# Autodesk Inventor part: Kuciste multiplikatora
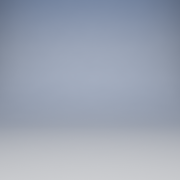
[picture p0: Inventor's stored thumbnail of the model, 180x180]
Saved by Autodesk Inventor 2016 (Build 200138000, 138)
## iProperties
Created: 2015-08
Part Number: Kuciste multiplikatora
Material: Generic
Document SubType Name: Modeling
Designer: Ugljesa
Density: 1 g/cm^3
Appearance: Default
Author: Ugljesa
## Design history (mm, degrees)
sketch "Sketch1"
  geometry: L1 (-70.533, -35.328)-(-30.533, -35.328); L2 (-30.533, -35.328)-(9.99, -69.331); L3 (-70.533, 44.672)-(-20.533, 44.672); L4 (-20.533, 44.672)-(38.788, 60.567); L5 (40.082, 55.737)-(-19.874, 39.672); L6 (-19.874, 39.672)-(-70.533, 39.672); L7 (-70.533, -30.328)-(-28.713, -30.328); L8 (-28.713, -30.328)-(13.204, -65.5); L9 (-70.533, 44.672)-(-70.533, 39.672); L10 (-70.533, -35.328)-(-70.533, -30.328); C1 r 12.5 at (58.199, -11.877) reference; A1 r 75 centre (58.199, -11.877) between (9.99, -69.331) and (38.788, 60.567); A2 r 70 centre (58.199, -11.877) between (13.204, -65.5) and (40.082, 55.737); 1 further point
  constraints: 20 end point, 4 point on circle, 2 centre point, 2 tangent, 2 vertical, 1 coincident, 1 horizontal, 3 other
  dimensions: "d0" = 80 distance of L3.start L1.start; "d1" = 15 deg angle of L4 L3; "d2" = 40 deg angle of L1 L2; "d3" = 75 radius of A1; "d4" = 50 distance of L3.start L3.end; "d5" = 40 distance of L1.start L1.end; "d6" = 5 radial gap between concentric circles of A1 A2; "d23" = 70 distance between parallel lines of L7 L6; "d25" = 5 distance between parallel lines of L4 L5
  node "Reference1"
workplane "Work Plane1"
workplane "Work Plane2"
extrude "Extrusion1" new body sketch "Sketch1" stored distance "d7" = 19.75; taper "d8" = 0 deg
sketch "Sketch2"
  geometry: L1 (120, 37)-(205, 25.054); L2 (205, 25.054)-(205, 37); L3 (205, 37)-(120, 37); L4 (50, 0)-(109.321, 0) reference; L5 (0, 0)-(0, 35) reference; 1 further point
  constraints: 6 end point, 1 perpendicular, 1 vertical
  dimensions: "d9" = 85 distance of L2.end L1.start; "d10" = 37 distance between parallel lines of L4 L3; "d11" = 8 deg angle of L3 L1; "d12" = 120 distance from line of L5 L1.start
extrude "Extrusion2" cut sketch "Sketch2" stored distance "d13" = 275.25; taper "d14" = 0 deg
sketch "Sketch3"
  geometry: L1 (0, 0)-(0, 149.596); 5 further points; 2 other entities
  constraints: 2 end point, 1 vertical, 2 other
extrude "Extrusion3" join sketch "Sketch3" distance "d15" = 5; taper "d16" = 0 deg
sketch "Sketch4"
  geometry: L1 (-30.523, -114.003)-(10, -80); L2 (10, -80)-(50, -80); L3 (50, -80)-(50, 0); L4 (50, 0)-(0, 0); L5 (0, 0)-(-59.321, 15.895); L6 (-84.231, -131.348)-(-84.231, 18.249); A1 r 75 centre (-78.732, -56.55) between (-84.231, -131.348) and (-30.523, -114.003); A2 r 75 centre (-78.732, -56.55) between (-59.321, 15.895) and (-84.231, 18.249); 1 further point
  constraints: 2 centre point, 2 end point, 1 vertical
extrude "Extrusion5" join sketch "Sketch4" distance "d19" = 5; taper "d20" = 0 deg
fillet "Fillet1" dims "d21" = 50
fillet "Fillet2" dims "d22" = 50
sketch "Sketch5"
  geometry: L1 (10.103, 51.176)-(-3.475, 46.891); L2 (-52.052, -37.533)-(-64.019, -37.533); L3 (-49.877, 49.276)-(-62.496, 49.276); L4 (58.199, -11.877)-(141.289, -11.877); L5 (132.872, -4.877)-(138.199, -4.877); L6 (132.872, -18.877)-(138.199, -18.877); C1 r 9 at (58.199, -11.877) reference; A1 r 75 centre (58.199, -11.877) between (9.99, -69.331) and (38.788, 60.567) reference; A2 r 75 centre (58.199, -11.877) between (132.872, -18.877) and (132.872, -4.877); A3 r 7 centre (138.199, -11.877) between (138.199, -18.877) and (138.199, -4.877); 1 further point
  constraints: 12 end point, 6 point on circle, 3 horizontal, 2 centre point, 2 tangent, 1 concentric, 1 point on line
  dimensions: "d27" = 14 distance of L5.start L6.start; "d28" = 14 diameter of L6.start L4; "d29" = 7 radius of A3; "d31" = 80 distance of L4.start A3.centre
extrude "Extrusion6" join sketch "Sketch5" distance "d32" = 15; taper "d33" = 0 deg
fillet "Fillet3" dims "d34" = 7
fillet "Fillet4" dims "d35" = 2
sketch "Sketch6"
  geometry: A1 r 7 centre (138.199, -11.877) between (138.199, -18.877) and (138.199, -4.877) reference; 1 further point
hole "Hole1" sketch "Sketch6" at (138.199, -11.877) diameter "d36" = 8; stored, may be unused: countersink angle "d40" = 90 deg, drill point angle "d42" = 118 deg; dims "d37" = 6, "d38" = 4, "d39" = 2, "d41" = 8
pattern_circular "Circular Pattern1" dims "d44" = 120 deg
pattern_circular "Circular Pattern2" dims "d47" = -110 deg
chamfer "Chamfer1" distance "d49" = 3; stored, may be unused: second distance "d50" = 2, angle "d51" = 45 deg
fillet "Fillet5" dims "d52" = 3
sketch "Sketch7"
  geometry: L1 (-30.533, 44.672)-(-30.533, 47.672); L2 (-30.533, 44.672)-(-45.533, 44.672); L3 (-45.533, 44.672)-(-45.533, 47.672); L4 (-70.533, 44.672)-(-27.115, 44.672) reference; L5 (-70.533, 39.672)-(-70.533, 44.672) reference; L6 (-70.533, 4.672)-(-14.799, 4.672); L7 (-48.731, -35.328)-(-70.533, -35.328) reference; L8 (-30.533, -35.328)-(-30.533, -38.328); L9 (-30.533, -35.328)-(-45.533, -35.328); L10 (-45.533, -35.328)-(-45.533, -38.328); A1 r 7.5 centre (-38.033, 47.672) between (-30.533, 47.672) and (-45.533, 47.672); A2 r 7.5 centre (-38.033, -38.328) between (-45.533, -38.328) and (-30.533, -38.328); 1 further point
  constraints: 14 end point, 5 symmetric about line, 4 point on circle, 2 centre point, 2 horizontal, 2 tangent, 1 collinear, 1 perpendicular, 1 vertical, 1 other
  dimensions: "d53" = 15 distance of L1.start L2.end; "d54" = 7.5 radius of A1 (derived); "d55" = 3 distance from line of L2 A1.centre; "d56" = 25 distance between parallel lines of L5 L3; "d57" = 40 distance between parallel lines of L7 L6
extrude "Extrusion7" join sketch "Sketch7" distance "d58" = 15; taper "d59" = 0 deg
fillet "Fillet6" dims "d60" = 7
fillet "Fillet7" dims "d61" = 5
fillet "Fillet8" dims "d62" = 2
sketch "Sketch8"
  geometry: A1 r 7.5 centre (-38.033, 47.672) between (-30.533, 47.672) and (-45.533, 47.672) reference; A2 r 7.5 centre (-38.033, -38.328) between (-45.533, -38.328) and (-30.972, -40.857) reference; 1 further point
hole "Hole2" sketch "Sketch8" at (-38.033, 47.672), (-38.033, -38.328) diameter "d63" = 8; stored, may be unused: countersink angle "d67" = 90 deg, drill point angle "d69" = 118 deg; dims "d64" = 6, "d65" = 4, "d66" = 2, "d68" = 8
body "Solid1"
node "Reference2"
